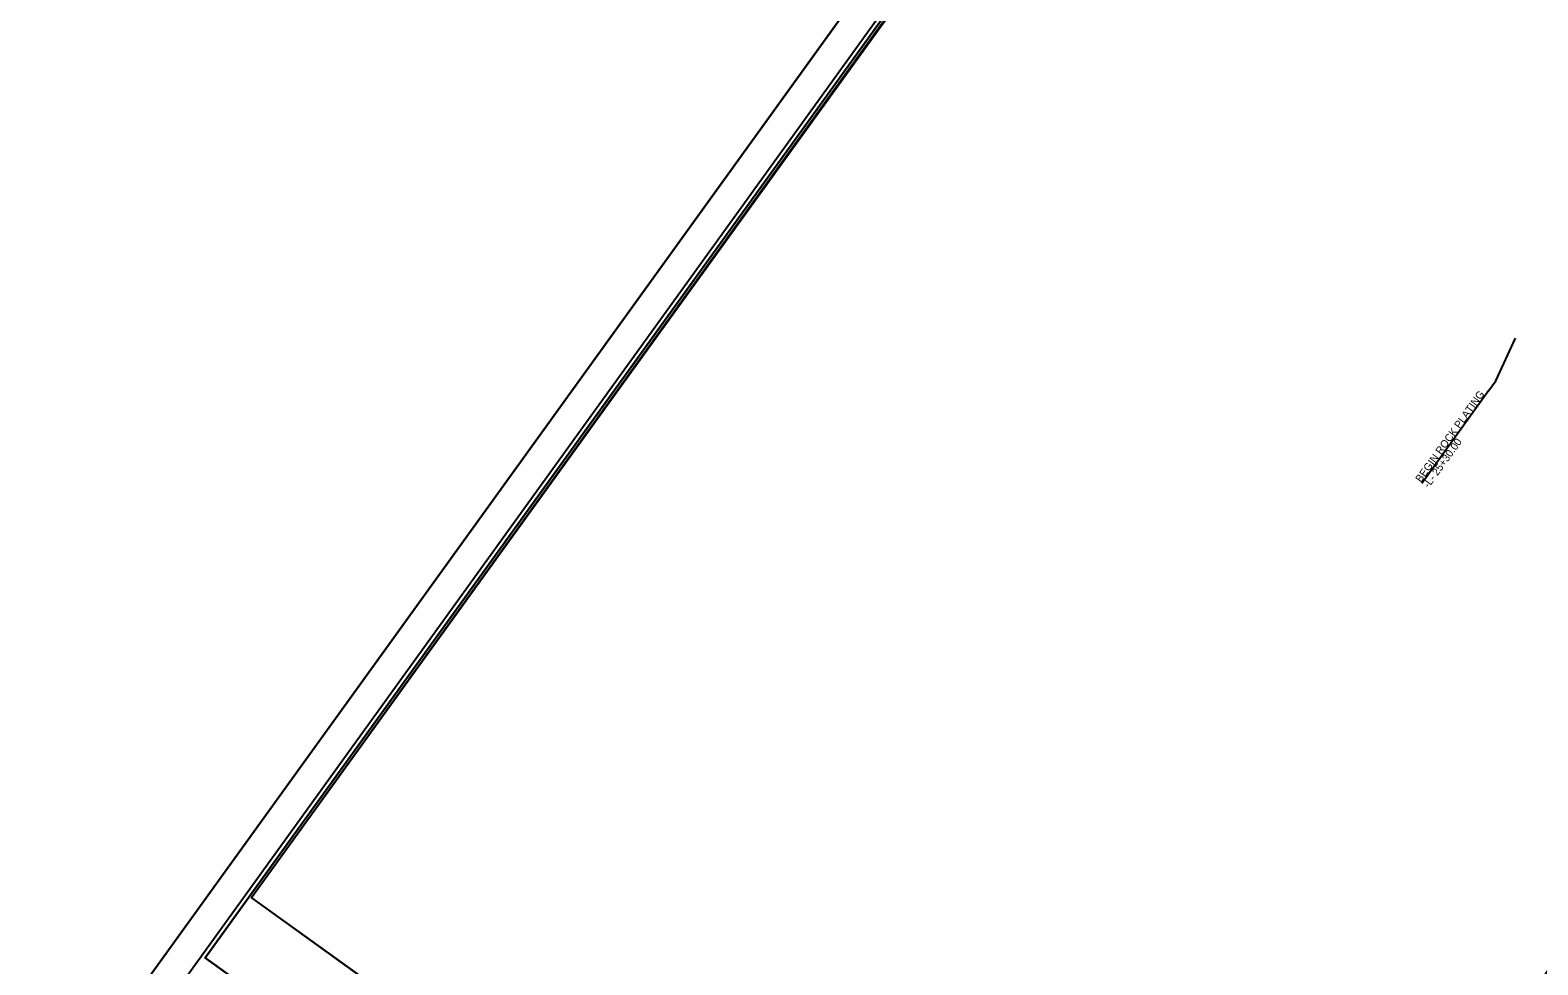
# Model space of a CAD drawing. Extents: x 2186840 to 2191350, y 386817 to 390793.
# Drawn here: x 2189477 to 2190474, y 387575 to 388192 of the extents above; entities that cross this region are included whole.
import ezdxf

# ---------------------------------------------------------------- set-up
doc = ezdxf.new("R2010")
doc.units = 0
for name, color, linetype in [('Prop Geotechnical Rock Plating Label', 7, 'Continuous'), ('Sheet Clip Boundary CELL', 7, 'Continuous'), ('Sheet Cutting Line CELL', 7, 'Continuous'), ('Sheet Layout Plan Border', 7, 'Continuous'), ('Sheet Plan CELL', 7, 'Continuous'), ('Sheet Plan Layout CELL', 7, 'Continuous'), ('Sheet Plot Border Inside CELL', 7, 'Continuous'), ('Sheet Plot Border Outside CELL', 7, 'Continuous')]:
    doc.layers.add(name, color=color, linetype=linetype)

msp = doc.modelspace()

# ---------------------------------------------------------------- linework, layer by layer
at = {"layer": 'Prop Geotechnical Rock Plating Label'}
msp.add_line((2190441.46, 387953.95), (2190397.25, 387892.65), dxfattribs=at)
msp.add_lwpolyline([(2190441.46, 387953.95), (2190446.23, 387960.56), (2190459.32, 387988.82)], dxfattribs=at)
at = {"layer": 'Sheet Clip Boundary CELL'}
msp.add_lwpolyline([(2189820.17, 387477.49), (2190138.13, 387247.68), (2190214.83, 387198.27), (2190505.63, 387605.8), (2190773.91, 387420.42), (2191313.5, 388179.15), (2190637.62, 388666.29), (2190501.89, 388478.1), (2190332.62, 388600.18), (2189623.63, 387618.74)], close=True, dxfattribs=at)
at = {"layer": 'Sheet Cutting Line CELL'}
msp.add_line((2190462.01, 388822.81), (2189477.28, 387457.36), dxfattribs=at)
at = {"layer": 'Sheet Layout Plan Border'}
msp.add_lwpolyline([(2190469.75, 387008.54), (2191313.6, 388178.64), (2190637.85, 388665.97), (2190536.83, 388525.9), (2190366.46, 388648.77), (2189623.63, 387618.74)], close=True, dxfattribs=at)
at = {"layer": 'Sheet Plan CELL'}
msp.add_line((2189592.9, 387579.24), (2189592.9, 387579.24), dxfattribs=at)
for points in [[(2190470.32, 388795.89), (2189592.9, 387579.24), (2190444.54, 386965.06), (2191321.95, 388181.69)], [(2190444.54, 386965.06), (2189592.91, 387579.2), (2190353.28, 388633.62), (2190475, 388545.85), (2190592.02, 388708.09), (2191321.95, 388181.69)]]:
    msp.add_lwpolyline(points, close=True, dxfattribs=at)
at = {"layer": 'Sheet Plan Layout CELL'}
msp.add_lwpolyline([(2189592.91, 387579.2), (2190444.54, 386965.06), (2191321.94, 388181.68), (2190641.84, 388672.15), (2190501.89, 388478.1), (2190330.36, 388601.81)], close=True, dxfattribs=at)
at = {"layer": 'Sheet Plot Border Inside CELL'}
msp.add_lwpolyline([(2190356.8, 386839.1), (2191331.28, 388190.36), (2190475.6, 388807.46), (2189501.11, 387456.2)], close=True, dxfattribs=at)
at = {"layer": 'Sheet Plot Border Outside CELL'}
msp.add_lwpolyline([(2190365.42, 386816.86), (2191350.15, 388182.31), (2190462.01, 388822.81), (2189477.28, 387457.36)], close=True, dxfattribs=at)

# ---------------------------------------------------------------- texts
at = {"layer": 'Prop Geotechnical Rock Plating Label'}
for s, p in [('BEGIN ROCK PLATING', (2190396.72, 387893.03)), ('-L- 25+30.00', (2190401.83, 387889.34))]:
    msp.add_text(s, height=5, rotation=54.20184, dxfattribs=at).set_placement(p)

doc.saveas('drawing.dxf')
